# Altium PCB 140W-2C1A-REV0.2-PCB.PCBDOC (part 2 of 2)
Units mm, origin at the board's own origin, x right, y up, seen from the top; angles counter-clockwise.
Board outline 106.75 x 106.95 mm, 4 copper layers (Top Layer, MidLayer1, MidLayer2, Bottom Layer); 108 components, 173 nets, 312 pads, 723 vias.
Unrouted connection lines stored in the file: 15.
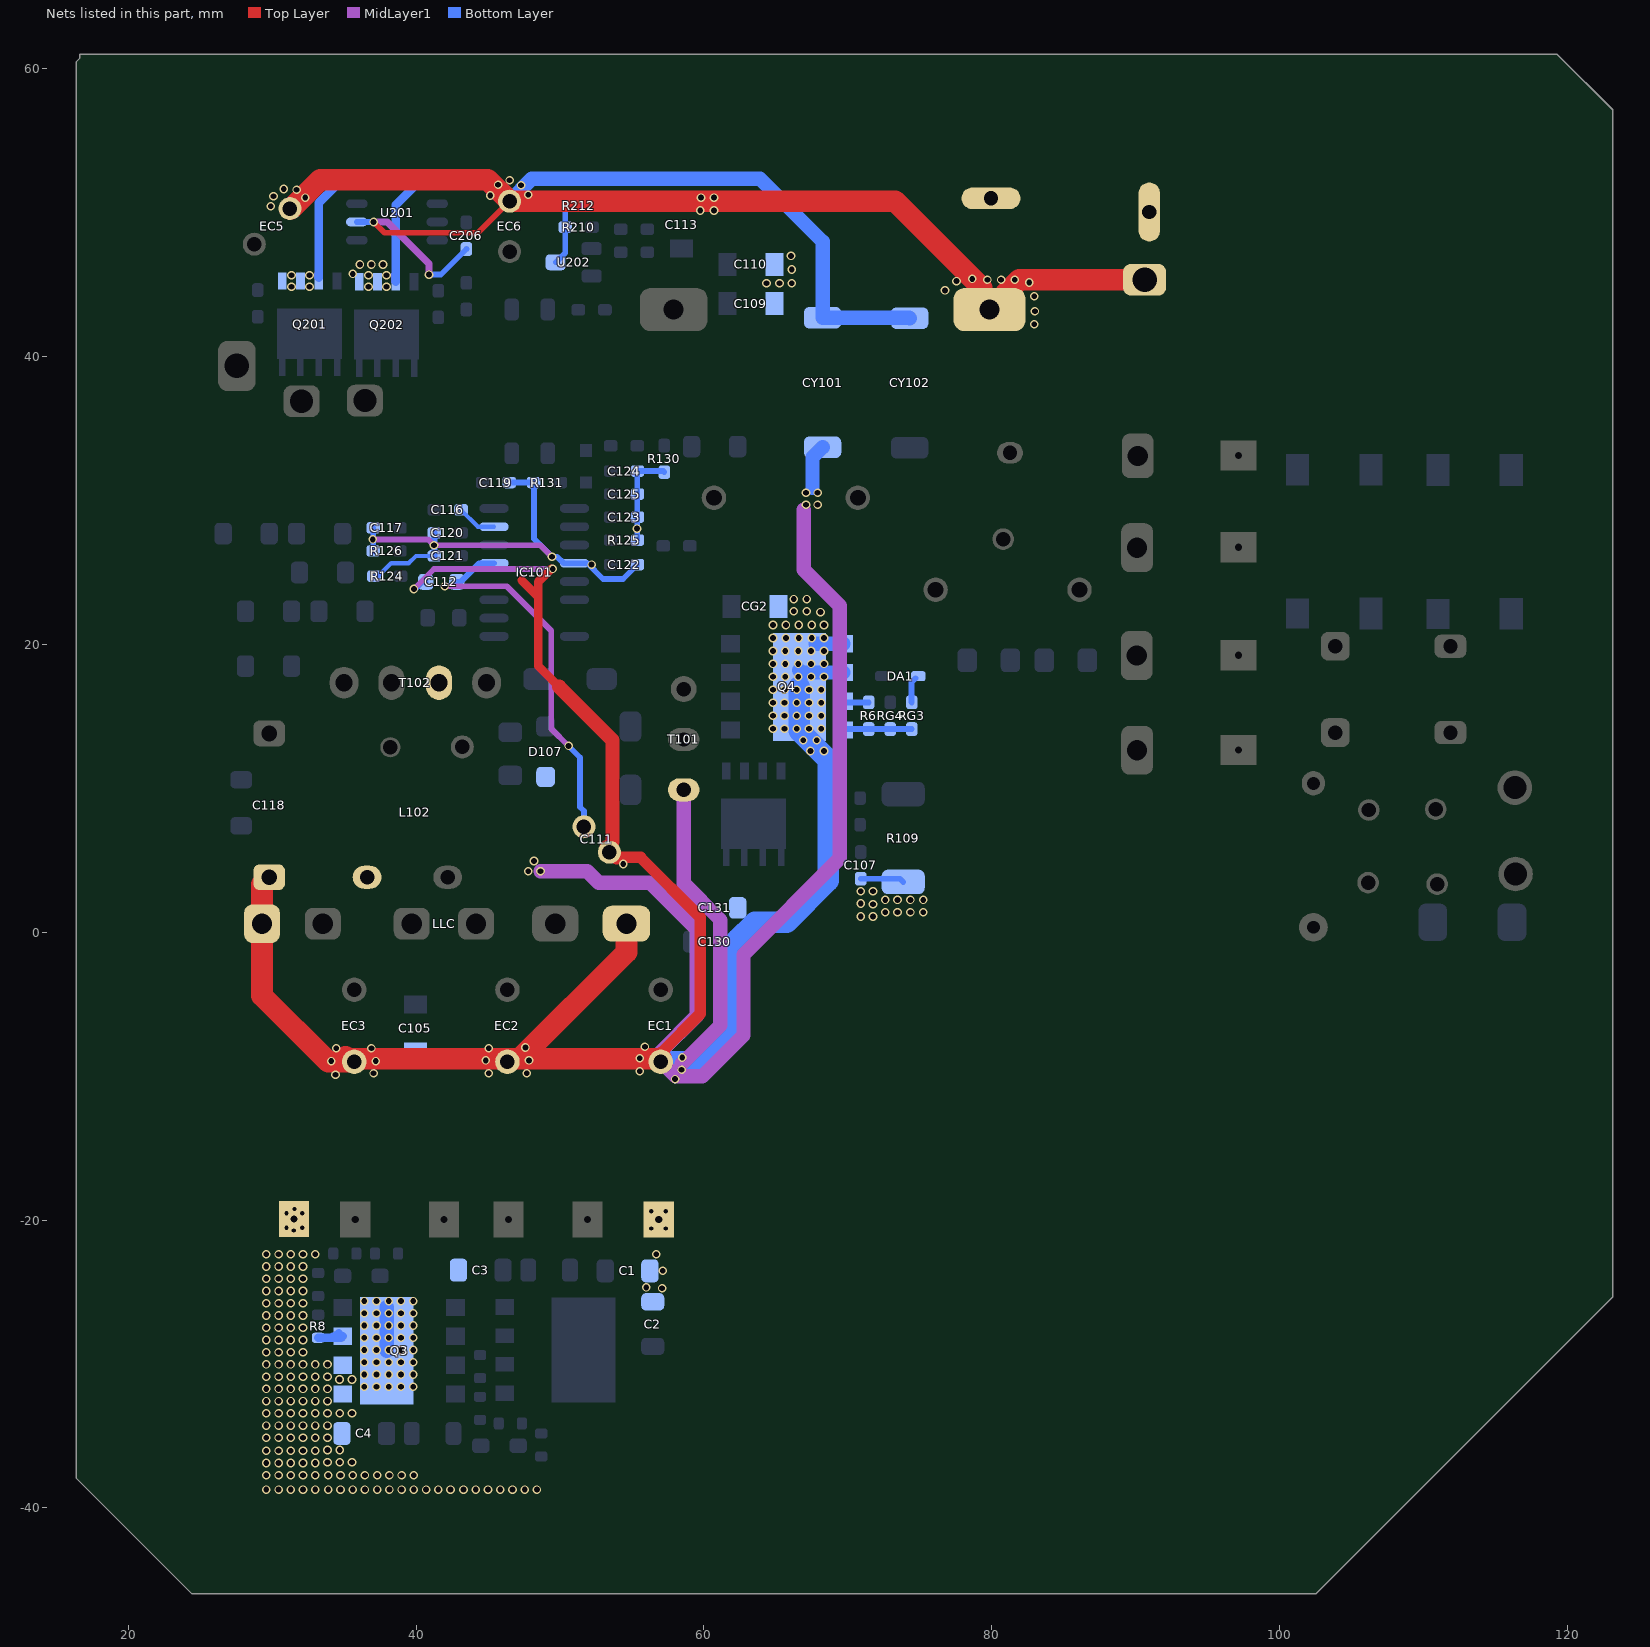
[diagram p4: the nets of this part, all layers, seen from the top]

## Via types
v1: diameter 0.6, hole 0.4, Top Layer to Bottom Layer, tented both sides, 674 vias
v2: diameter 0.65, hole 0.5, Top Layer to Bottom Layer, 27 vias
v3: diameter 0.5, hole 0.3, Top Layer to Bottom Layer, 22 vias

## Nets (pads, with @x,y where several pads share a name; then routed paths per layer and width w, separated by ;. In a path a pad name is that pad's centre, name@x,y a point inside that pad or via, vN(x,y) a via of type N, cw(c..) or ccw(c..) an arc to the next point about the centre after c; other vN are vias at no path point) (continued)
PGND: C1.2 C2.2 C3.1 C4.2 C105.1 C107.1 C111.2 C112.2 C117.1 C118.1 C119.2 C120.1 C121.1 C122.1 C123.1 C124.1 C125.1 C130.2 C131.2 CG2.1 CY101.2 EC1.2 EC2.2 EC3.2 IC101.4 L102.2 LLC.1 LLC.6 pad.2@31.52,-19.925 pad.2@56.87,-19.95 Q3.S Q4.S R6.1 R8.1 R109.1 R124.1 R125.1 R126.1 R130.2 R131.1 T101.3 T102.3 | length 291.6
  Top Layer w0.6: 47.35,24.45 48.5,23.3 ; v1@49.4,25.25 48.5,24.35 48.5,23.3 ; 49.95,17.05 48.5,18.5 48.5,23.3
  Top Layer w0.8: C111.2@53.95,5.2 55.6,5.2 59.75,1.05 59.75,-5.65 57.05,-8.35 EC1.2@57.05,-8.8
  Top Layer w1: 49.95,17.05 53.65,13.35 C111.2@53.65,6.3 ; C111.2@53.25,5.9 C111.2@53.95,5.2
  Top Layer w1.5: C118.1@29.797,3.823 29.297,3.323 LLC.6@29.297,0.598 29.297,-4.397 33.9,-9 EC3.2@35.7,-9 ; EC3.2@35.1,-8.651 35.249,-8.8 47.2,-8.8 ; LLC.1@54.622,0.598 54.622,-1.378 47.2,-8.8 ; EC1.2@57.05,-8.8 47.2,-8.8
  MidLayer1 w0.4: v1(37,27.3) 40.85,27.3 v1(41.25,26.9) 48.65,26.9 v1(49.45,26.1) ; v1(39.85,23.85) 41.25,25.25 v1(49.5,25.25)
  MidLayer1 w1: C118.1@29.797,3.823 C118.1@29.799,3.825 ; v1(48.65,4.25) 51.9,4.25 52.7,3.45 56.25,3.45 59.5,0.2 59.5,-5.8 56.95,-8.35 56.95,-8.9 58.05,-10 59.9,-10 62.75,-7.15 62.75,-1.55 69.45,5.15 69.45,22.7 66.95,25.2 66.95,29.35 ; 58.475,-9.125 61.15,-6.45 61.15,0.85 58.6,3.4 T101.3@58.6,9.9
  Bottom Layer w0.3: R124.1@37.075,24.75 37.376,24.75 38.276,25.65 39.5,25.65 40,26.15 C121.1@41.275,26.15
  Bottom Layer w0.4: R126.1@37.025,26.5 C117.1@37.025,28.1 ; v1@39.95,23.85 40.45,24.35 C112.2@40.675,24.35 ; C121.1@41.275,26.15 C120.1@41.275,27.75 ; C119.2@46.475,31.25 R131.1@48.175,31.25 ; R131.1@48.2,31.15 48.2,27.35 v1(49.45,26.1) 49.8,26.1 50.26,25.64 IC101.4@51.007,25.64 51.91,25.64 53,24.55 54.375,24.55 C122.1@55.375,25.55 ; R125.1@55.375,27.3 C123.1@55.375,28.85 C125.1@55.375,30.45 C124.1@55.375,32.05 57.175,32.05 R130.2@57.25,31.975 ; Q4.S@69.7,16.05 69.775,15.975 R6.1@71.45,15.975 ; C107.1@70.9,3.725 73.625,3.725 R109.1@73.85,3.5
  Bottom Layer w0.6: R8.1@33.198,-28.175 34.798,-28.175 Q3.S@34.898,-28.075 ; 33.882,-28.175 ccw(c33.882,-27.109) Q3.S@34.636,-27.863
  Bottom Layer w1: Q3.S@37.961,-29.075 Q3.S@37.961,-26.062 ; Q4.S@66.637,18.2 66.787,18.05 Q4.S@69.7,18.05 ; 67.55,30.9 67.55,33.001 CY101.2@68.247,33.698 ; Q4.S@67.775,20.05 Q4.S@69.7,20.05
  Bottom Layer w1.5: EC1.2@57,-9 59.9,-9 62.25,-6.65 62.25,-0.6 63.55,0.7 65.75,0.7 68.65,3.6 68.65,12 66.637,14.013 Q4.S@66.637,17.05
  other v1: 29.598,-38.725 30.448,-38.725 31.298,-38.725 32.148,-38.725 32.998,-38.725 33.898,-38.725 34.748,-38.725 35.598,-38.725 36.448,-38.725 37.298,-38.725 38.148,-38.725 38.998,-38.725 39.848,-38.725 40.698,-38.725 41.548,-38.725 42.398,-38.725 43.298,-38.725 44.148,-38.725 44.998,-38.725 45.848,-38.725 46.698,-38.725 47.548,-38.725 48.398,-38.725 29.598,-37.725 30.448,-37.725 31.298,-37.725 32.148,-37.725 32.998,-37.725 33.898,-37.725 34.748,-37.725 35.598,-37.725 36.448,-37.725 37.298,-37.725 38.148,-37.725 38.998,-37.725 39.848,-37.725 29.598,-36.875 30.448,-36.875 31.298,-36.875 32.148,-36.875 32.998,-36.875 33.848,-36.825 34.698,-36.825 35.548,-36.825 29.598,-36.025 30.448,-36.025 31.298,-36.025 32.148,-36.025 32.998,-36.025 33.848,-35.975 34.698,-35.975 29.598,-35.125 30.448,-35.125 31.298,-35.125 32.148,-35.125 32.998,-35.125 33.848,-35.125 29.598,-34.275 30.448,-34.275 31.298,-34.275 32.148,-34.275 32.998,-34.275 33.848,-34.275 29.598,-33.425 30.448,-33.425 31.298,-33.425 32.148,-33.425 32.998,-33.425 33.848,-33.425 34.698,-33.425 35.548,-33.425 29.598,-32.575 30.448,-32.575 31.298,-32.575 32.148,-32.575 32.998,-32.575 33.848,-32.575 29.598,-31.725 30.448,-31.725 31.298,-31.725 32.148,-31.725 32.998,-31.725 33.848,-31.725 36.398,-31.575 37.248,-31.575 38.098,-31.575 38.948,-31.575 39.798,-31.575 34.685,-31.075 35.548,-31.075 29.598,-30.875 30.448,-30.875 31.298,-30.875 32.148,-30.875 32.998,-30.875 33.848,-30.875 36.398,-30.725 37.248,-30.725 38.098,-30.725 38.948,-30.725 39.798,-30.725 29.598,-30.025 30.448,-30.025 31.298,-30.025 32.148,-30.025 32.998,-30.025 33.848,-30.025 36.398,-29.875 37.248,-29.875 38.098,-29.875 38.948,-29.875 39.798,-29.875 29.598,-29.175 30.448,-29.175 31.298,-29.175 32.148,-29.175 36.398,-29.025 37.248,-29.025 38.098,-29.025 38.948,-29.025 39.798,-29.025 29.598,-28.325 30.448,-28.325 31.298,-28.325 32.148,-28.325 36.398,-28.175 37.248,-28.175 38.098,-28.175 38.948,-28.175 39.798,-28.175 29.598,-27.475 30.448,-27.475 31.298,-27.475 32.148,-27.475 36.398,-27.325 37.248,-27.325 38.098,-27.325 38.948,-27.325 39.798,-27.325 29.598,-26.625 30.448,-26.625 31.298,-26.625 32.148,-26.625 36.398,-26.475 37.248,-26.475 38.098,-26.475 38.948,-26.475 39.798,-26.475 29.598,-25.775 30.448,-25.775 31.298,-25.775 32.148,-25.775 36.398,-25.625 37.248,-25.625 38.098,-25.625 38.948,-25.625 39.798,-25.625 29.598,-24.925 30.448,-24.925 31.298,-24.925 32.148,-24.925 57.098,-24.725 55.998,-24.675 29.598,-24.075 30.448,-24.075 31.298,-24.075 32.148,-24.075 57.148,-23.525 29.598,-23.225 30.448,-23.225 31.298,-23.225 32.148,-23.225 29.598,-22.375 30.448,-22.375 31.298,-22.375 32.148,-22.375 32.998,-22.375 56.698,-22.375 58,-10.2 34.4,-9.9 37.05,-9.8 45.05,-9.8 47.7,-9.8 55.55,-9.65 58.45,-9.55 34.1,-8.95 37.2,-8.95 44.85,-8.9 47.85,-8.9 55.55,-8.75 58.5,-8.7 34.45,-8.05 36.9,-8.05 45.05,-8.05 47.6,-8 55.9,-7.95 70.9,1.1 71.75,1.1 72.6,1.4 73.45,1.4 74.35,1.4 75.25,1.4 71.75,1.95 70.9,2 72.6,2.25 73.45,2.25 74.35,2.25 75.25,2.25 70.9,2.85 71.75,2.85 47.8,4.25 54.4,4.75 48.2,4.95 67.4,12.6 68.35,12.6 66.9,13.35 67.85,13.35 64.8,14.15 65.6,14.15 66.45,14.15 67.3,14.15 68.15,14.15 64.8,15.05 65.6,15.05 66.45,15.05 67.3,15.05 68.15,15.05 64.8,15.95 65.6,15.95 66.45,15.95 67.3,15.95 68.15,15.95 64.8,16.85 65.6,16.85 66.45,16.85 67.3,16.85 68.15,16.85 64.8,17.75 65.65,17.75 66.55,17.75 67.45,17.75 68.35,17.75 64.8,18.65 65.65,18.65 66.55,18.65 67.45,18.65 68.35,18.65 64.8,19.55 65.65,19.55 66.55,19.55 67.45,19.55 68.35,19.55 64.8,20.45 65.7,20.45 66.6,20.45 67.5,20.45 68.35,20.45 64.8,21.35 65.7,21.35 66.6,21.35 67.5,21.35 68.35,21.35 68.1,22.25 66.25,22.3 67.15,22.3 66.25,23.15 67.15,23.15 52.2,25.55 55.35,28.05 67.1,29.7 67.9,29.7 67.1,30.55 67.9,30.55
  other v3: 31.5,-20.725 56.35,-20.575 57.35,-20.575 30.995,-20.525 32.1,-20.525 30.995,-19.525 32.1,-19.525 56.35,-19.375 57.35,-19.375 31.55,-19.225
Q101_1: 
Q101_2: Q4.G R6.2 RG3.1 RG4.1 | length 4.8
  Bottom Layer w0.4: Q4.G@69.7,14.05 69.775,14.125 RG4.1@72.95,14.125 RG3.1@74.45,14.125
Q101_3: 
Q101_4: 
RG3_2: DA1.1 RG3.2 | length 1.8
  Bottom Layer w0.4: RG3.2@74.45,15.975 74.425,16 74.425,17.375 DA1.1@74.7,17.65
SCL: 
SCL1: 
SCL2: 
SDA: 
SDA1: 
SDA2: 
SGND: C109.1 C110.2 C113.1 C206.2 CY101.1 CY102.1 EC5.2 EC6.2 pad.0@79.95,51 pad.0@90.95,50.05 pad.0@90.625,45.342 pad.2@79.85,43.267 Q201.1S Q201.2S Q201.3S Q202.1S Q202.2S Q202.3S R210.1 R212.1 U201.2GND U201.4SSB U201.5SSA U202.2 | length 146.2
  Top Layer w0.4: EC5.2@31.237,50.287 EC5.2@31.675,49.85 ; v1(37.05,49.35) 37.8,48.6 44.3,48.6 EC6.2@46.5,50.8
  Top Layer w1.5: EC5.2@31.237,50.287 31.337,50.287 33.354,52.304 44.996,52.304 EC6.2@46.5,50.8 73.3,50.8 79.3,44.8 ; pad.2@79.85,43.267 81.925,45.342 pad.0@90.625,45.342
  MidLayer1 w0.5: v1(37.05,49.35) 38,49.35 40.9,46.45 v1(40.9,45.7)
  Bottom Layer w0.4: U201.2GND@35.886,49.357 35.893,49.35 v1(37.05,49.35) ; v1(40.9,45.7) 41.725,45.7 C206.2@43.5,47.475 ; EC6.2@46.5,50.8 47.05,50.25 R212.1@50.375,50.25 ; U202.2@49.7,46.55 50.375,47.225 R210.1@50.375,49 R212.1@50.375,50.5
  Bottom Layer w0.6: Q201.3S@33.24,45.5 33.24,50.69 34.447,51.897 U201.4SSB@35.886,51.897 ; Q202.3S@38.59,45.2 38.59,50.54 39.947,51.897 U201.5SSA@41.473,51.897
  Bottom Layer w1: EC6.2@46.5,50.8 48.05,52.35 63.9,52.35 68.247,48.003 CY101.1@68.247,42.698 74.272,42.698 CY102.1@74.297,42.673
  other v1: 82.95,42.25 83,43.15 82.95,44.2 76.75,44.6 31.35,44.85 32.6,44.85 36.7,44.85 37.95,44.85 64.35,45.1 65.25,45.1 66.1,45.1 82.6,45.15 77.55,45.25 79.7,45.35 80.65,45.35 81.6,45.35 78.65,45.4 31.35,45.65 32.6,45.65 36.7,45.65 37.95,45.65 35.6,45.75 66.1,46.05 36.1,46.4 36.9,46.4 37.7,46.4 66.05,47 59.75,50.15 60.7,50.15 29.9,50.45 32.3,51.05 59.8,51.05 60.7,51.05 30.1,51.15 45.15,51.2 47.8,51.25 31.7,51.6 30.8,51.65 47.3,51.9 45.7,51.95 46.5,52.25
SNSCURLLC: C116.2 IC101.15 | length 2.8
  Bottom Layer w0.3: C116.2@43.125,29.35 44.295,28.18 IC101.15@45.419,28.18
VCC: C111.1 C112.1 D107.2 IC101.13 | length 27.3
  MidLayer1 w0.4: v1(42,24.05) 46.3,24.05 49.4,20.95 49.4,14.15 v1(50.6,12.95)
  Bottom Layer w0.4: v1(42,24.05) 42.525,24.05 C112.1@42.825,24.35 43.1,24.35 44.39,25.64 IC101.13@45.419,25.64 ; v1(50.6,12.95) 51.4,12.15 51.4,8.7 51.666,8.434 C111.1@51.666,7.334
VDD: 
VDRV: 
VDRV1: 
VDRV2: 
VIN20: 
pads on no net: IC101.7 IC101.12 L102.4

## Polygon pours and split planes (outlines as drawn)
PGND on Top Layer "Keep-Out Layer-No Net" (solid, remove dead copper, pour order 533): 57.898,-25.825 57.448,-26.275 55.948,-26.275 55.648,-25.975 55.648,-21.475 55.798,-21.325 55.798,-20.575 57.498,-20.575 57.898,-20.975
NetC101_1 on Top Layer "Keep-Out Layer-No Net" (solid, remove dead copper, pour order 531): 20 vertices, not listed, extent 48.698,-39.725 57.448,-20.675
PGND on Top Layer "Keep-Out Layer-No Net" (solid, remove dead copper, pour order 529): 20 vertices, not listed, extent 29.098,-39.725 49.198,-20.625
NetC108_1 on Top Layer "Keep-Out Layer-No Net" (solid, remove dead copper, pour order 527): 42.998,-21.425 44.398,-22.825 44.398,-24.525 45.598,-25.725 45.598,-27.725 45.398,-27.925 42.598,-27.925 42.048,-27.375 42.048,-23.325 40.898,-22.175 40.898,-20.625 42.848,-20.625 42.998,-20.775
PGND on Top Layer "Bottom Layer-No Net 1" (solid, remove dead copper, pour order 445): 40.45,10.45 41.1,9.8 41.1,7 39.75,5.65 37.4,3.3 31.9,3.3 26,3.3 25.6,3.7 25.6,9.15 26.65,10.2 26.9,10.45 32.75,10.45
NetQ201_5 on Top Layer "Bottom Layer-No Net 1" (solid, remove dead copper, pour order 417): 22 vertices, not listed, extent 34.8,35.8 41.35,43.55
NetQ201_7 on Top Layer "Bottom Layer-No Net 1" (solid, remove dead copper, pour order 415): 19 vertices, not listed, extent 29.4,35.8 34.95,43.55
+20V on Top Layer "Bottom Layer-No Net 1" (solid, remove dead copper, pour order 413): 45.5,48.55 46.9,48.55 47.15,48.3 48.05,48.3 57.15,48.3 60.8,44.65 61.35,44.1 61.35,42.95 61.35,42.1 61,41.75 59.85,41.75 45.95,41.75 44.8,42.9 44.8,47.85 45.5,48.55
+20V on Top Layer "Bottom Layer-No Net 1" (solid, remove dead copper, pour order 411): 23 vertices, not listed, extent 25.25,36.95 29.75,49.45
SGND on Top Layer "Bottom Layer-No Net 1" (solid, remove dead copper, pour order 409): 47 vertices, not listed, extent 28.55,41.8 92.9,53.05
PGND on Top Layer "Bottom Layer-No Net 1" (solid, remove dead copper, pour order 373): 17 vertices, not listed, extent 30.5,2.65 37.75,5.3
PGND on Top Layer "Bottom Layer-No Net 1" (solid, remove dead copper, pour order 353): 29 vertices, not listed, extent 25.55,19.9 58.6,34.4
NetC108_1 on Top Layer "Bottom Layer-No Net 1" (solid, remove dead copper, pour order 347): 18 vertices, not listed, extent 38.2,-0.5 43.25,4.7
PGND on Top Layer "Bottom Layer-No Net 1" (solid, remove dead copper, pour order 345): 67.2,28.95 67.9,28.25 67.9,24.65 69.2,23.35 69.25,23.3 69.25,22.75 64.45,22.75 64.4,22.8 62.25,24.95 62.25,27.5 63.7,28.95
NetC101_1 on Top Layer "Bottom Layer-No Net 1" (solid, remove dead copper, pour order 343): 19 vertices, not listed, extent 58,4.05 66.05,9.35
PGND on Top Layer "Bottom Layer-No Net 1" (solid, remove dead copper, pour order 341): 32 vertices, not listed, extent 48.2,-5.1 60.15,26.45
PGND on Top Layer "Bottom Layer-No Net 1" (solid, remove dead copper, pour order 339): 68 vertices, not listed, extent 25.6,-11.35 75.55,5.3
PGND on Top Layer "Bottom Layer-No Net 1" (solid, remove dead copper, pour order 337): 18 vertices, not listed, extent 64.4,4.05 69.95,23.5
NetC114_1 on Top Layer "Keep-Out Layer-No Net" (solid, remove dead copper, pour order 277): 22 vertices, not listed, extent 28.5,12.75 36,18.4
NetL102_2 on Top Layer "Keep-Out Layer-No Net" (solid, remove dead copper, pour order 271): 38.2,18.55 39,18.55 39.2,18.35 39.2,12.4 38.85,12.05 37.7,12.05 37.3,12.45 37.3,18.1 37.75,18.55
NetBD101_2 on Top Layer "Keep-Out Layer-No Net" (solid, remove dead copper, pour order 265): 111.5,23.95 117.55,23.95 118,23.5 118,23.1 118,18.5 117.5,18 117.2,18 110.5,18 110.1,18.4 110.05,18.45 110.05,18.65 110.05,23.55 110.4,23.9 110.45,23.95 111.4,23.95
NetBD101_4 on Top Layer "Keep-Out Layer-No Net" (solid, remove dead copper, pour order 250): 117.6,33.95 118,33.55 118,28.6 117.25,27.85 102.6,27.85 100.45,25.7 97.35,25.7 97.35,27.75 97.4,27.8 98.65,27.8 99.1,28.25 99.1,30.35 100.05,31.3 100.05,33.35 100.65,33.95
NetBD101_3 on Top Layer "Keep-Out Layer-No Net" (solid, remove dead copper, pour order 264): 106.9,22.2 107.55,21.55 107.55,18.45 107.1,18 98.65,18 98.45,18.2 97.7,18.2 97.7,20.25 97.75,20.3 98.65,20.3 98.8,20.45 98.8,21.5 99.5,22.2
NetCX101_2 on Top Layer "Keep-Out Layer-No Net" (solid, remove dead copper, pour order 266): 47 vertices, not listed, extent 98.1,-0.9 107.1,15.1
NetCX101_1 on Top Layer "Keep-Out Layer-No Net" (solid, remove dead copper, pour order 246): 21 vertices, not listed, extent 101.55,7.35 113.35,14.95
NetCN101_N on Top Layer "Keep-Out Layer-No Net" (solid, remove dead copper, pour order 243): 117.45,11.7 117.75,11.4 117.75,9.35 117.25,8.85 113.9,8.85 112.55,7.5 110.2,7.5 109.85,7.85 109.85,9 111.7,10.85 114.05,10.85 114.9,11.7
NetBD1 on Top Layer "Keep-Out Layer-No Net" (solid, remove dead copper, pour order 269): 82.35,34.55 82.8,34.1 82.8,32.9 82.45,32.55 74.15,32.55 65.05,32.55 60.7,28.2 60.7,16.55 60.1,15.95 57.35,15.95 57.15,16.15 57.15,29.25 62.45,34.55
NetBD101_4 on Top Layer "Keep-Out Layer-No Net" (solid, remove dead copper, pour order 279): 23 vertices, not listed, extent 68.75,8.65 92.25,31.05
PGND on Bottom Layer "Keep-Out Layer-No Net" (solid, remove dead copper, pour order 545): 57.898,-20.575 57.898,-25.825 57.448,-26.275 55.798,-26.275 55.648,-26.125 55.648,-24.025 55.648,-21.475 55.798,-21.325 55.798,-20.575 57.848,-20.575
NetC101_1 on Bottom Layer "Keep-Out Layer-No Net" (solid, remove dead copper, pour order 543): 20 vertices, not listed, extent 48.698,-39.725 57.448,-19.925
113 on Bottom Layer "Keep-Out Layer-No Net" (solid, remove dead copper, pour order 541): 46.248,-22.675 48.198,-22.675 48.348,-22.825 48.348,-23.175 48.348,-24.125 48.198,-24.275 47.798,-24.275 45.598,-24.275 45.498,-24.175 45.448,-24.125 45.448,-23.875 45.448,-22.825 45.598,-22.675 45.848,-22.675
PGND on Bottom Layer "Keep-Out Layer-No Net" (solid, remove dead copper, pour order 539): 39 vertices, not listed, extent 29.098,-39.725 49.198,-20.825
NetC108_1 on Bottom Layer "Keep-Out Layer-No Net" (solid, remove dead copper, pour order 537): 46.798,-25.475 46.898,-25.575 46.898,-28.475 46.748,-28.625 43.898,-28.625 43.448,-29.075 43.448,-35.375 43.198,-35.625 42.198,-35.625 41.998,-35.425 41.998,-25.575 42.098,-25.475
115 on Bottom Layer "Keep-Out Layer-No Net" (solid, remove dead copper, pour order 535): 38.648,-34.025 40.098,-34.025 40.248,-34.175 40.248,-34.275 40.248,-35.475 40.098,-35.625 39.898,-35.625 37.498,-35.625 37.398,-35.525 37.348,-35.475 37.348,-35.075 37.348,-34.175 37.448,-34.075 37.498,-34.025 38.398,-34.025
SGND on Bottom Layer "Bottom Layer-No Net 1" (solid, remove dead copper, pour order 407): 18 vertices, not listed, extent 69.75,41.8 92.9,53.05
SGND on Bottom Layer "Bottom Layer-No Net 1" (solid, remove dead copper, pour order 405): 37 vertices, not listed, extent 28.95,41.8 75.7,53.05
SGND on Bottom Layer "Bottom Layer-No Net 1" (solid, remove dead copper, pour order 403): 19 vertices, not listed, extent 57.3,42.45 66.45,51.45
+20V on Bottom Layer "Bottom Layer-No Net 1" (solid, remove dead copper, pour order 401): 20 vertices, not listed, extent 54.15,41.75 62.65,49.587
+20V on Bottom Layer "Bottom Layer-No Net 1" (solid, remove dead copper, pour order 399): 18 vertices, not listed, extent 44.2,45.75 48.2,48.8
SGND on Bottom Layer "Bottom Layer-No Net 1" (solid, remove dead copper, pour order 397): 20 vertices, not listed, extent 35.3,44.55 39,47.3
+20V on Bottom Layer "Bottom Layer-No Net 1" (solid, remove dead copper, pour order 395): 18 vertices, not listed, extent 25.25,36.95 29.75,50.05
SGND on Bottom Layer "Bottom Layer-No Net 1" (solid, remove dead copper, pour order 393): 27 vertices, not listed, extent 28.95,44.55 33.65,52.75
NetQ201_7 on Bottom Layer "Bottom Layer-No Net 1" (solid, remove dead copper, pour order 391): 18 vertices, not listed, extent 29,35.8 34.95,43.55
NetQ201_5 on Bottom Layer "Bottom Layer-No Net 1" (solid, remove dead copper, pour order 389): 18 vertices, not listed, extent 34.8,35.8 41.35,43.55
VCC on Bottom Layer "Bottom Layer-No Net 1" (solid, remove dead copper, pour order 351): 30 vertices, not listed, extent 48.25,6.25 52.65,11.55
NetBD1 on Bottom Layer "Bottom Layer-No Net 1" (solid, remove dead copper, pour order 335): 17 vertices, not listed, extent 54.15,14.05 59.7,17.95
PGND on Bottom Layer "Bottom Layer-No Net 1" (solid, remove dead copper, pour order 333): 53.4,6.6 53.85,6.6 54.25,6.2 54.7,5.75 54.7,4.5 54.45,4.25 53.55,4.25 53.15,4.25 52.45,4.95 52.3,5.1 52.3,5.55 52.3,5.7 53.15,6.55 53.2,6.6 53.3,6.6
NetC107_2 on Bottom Layer "Top Overlay-No Net" (hatched 90Degree grid 0.1 track 0.203, pour order 245): -274.888,-89.395 -274.782,-89.288 -274.742,-89.288
NetD107_1 on Bottom Layer "Bottom Solder-No Net" (solid, remove dead copper, pour order 254): 17 vertices, not listed, extent 43.872,13.2 47.225,18.423
NetCN101_L on Bottom Layer "Keep-Out Layer-No Net" (solid, remove dead copper, pour order 240): 116.55,5.45 117.55,5.45 117.95,5.05 117.95,-0.5 117.6,-0.85 115.45,-0.85 115.05,-0.45 115.05,4.15 115.05,4.75 115.65,5.35 115.75,5.45 116.25,5.45
NetF101_2 on Bottom Layer "Keep-Out Layer-No Net" (solid, remove dead copper, pour order 241): 110.8,4.55 111.45,4.55 111.75,4.25 111.75,3.1 111.75,-0.55 111.45,-0.85 109.9,-0.85 109.5,-0.45 109.5,3.85 110.2,4.55
NetCN101_N on Bottom Layer "Keep-Out Layer-No Net" (solid, remove dead copper, pour order 242): 117.45,11.7 117.75,11.4 117.75,9.1 117.3,8.65 114.05,8.65 112.9,7.5 110.2,7.5 109.85,7.85 109.85,9 111.7,10.85 114.05,10.85 114.9,11.7
NetCX101_2 on Bottom Layer "Keep-Out Layer-No Net" (solid, remove dead copper, pour order 247): 27 vertices, not listed, extent 97.85,-0.9 107.1,15.1
NetBD101_4 on Bottom Layer "Keep-Out Layer-No Net" (solid, remove dead copper, pour order 260): 106.05,33.95 107.65,33.95 107.85,33.75 107.85,31.25 107.6,31 104.95,31 104.7,31.25 104.65,31.3 104.65,33.2 104.65,33.7 104.85,33.9 104.9,33.95 105.7,33.95
NetBD101_1 on Bottom Layer "Keep-Out Layer-No Net" (solid, remove dead copper, pour order 261): 34 vertices, not listed, extent 97.55,27.85 112.8,34.15
NetBD101_3 on Bottom Layer "Keep-Out Layer-No Net" (solid, remove dead copper, pour order 263): 20 vertices, not listed, extent 98.3,18 107.55,23.95
NetBD101_2 on Bottom Layer "Keep-Out Layer-No Net" (solid, remove dead copper, pour order 262): 117.55,23.95 118,23.5 118,18.55 117.45,18 110.5,18 110.05,18.45 110.05,23.55 110.45,23.95
NetCX101_1 on Bottom Layer "Keep-Out Layer-No Net" (solid, remove dead copper, pour order 244): 21 vertices, not listed, extent 101.55,7.35 113.35,14.95
NetBD101_4 on Bottom Layer "Keep-Out Layer-No Net" (solid, remove dead copper, pour order 259): 117.7,33.85 118,33.55 118,30.05 117.3,29.35 114.9,29.35 114.35,29.9 114.35,33.6 114.6,33.85
PGND on Bottom Layer "Keep-Out Layer-No Net" (solid, remove dead copper, pour order 276): 71.75,4.35 75.25,4.35 75.55,4.05 75.55,-0.9 75.15,-1.3 70.9,-1.3 70.5,-0.9 70.5,4.15 70.65,4.3 70.7,4.35 71.5,4.35
NetBD101_4 on Bottom Layer "Keep-Out Layer-No Net" (solid, remove dead copper, pour order 278): 72.4,12 75.2,12 75.45,11.75 75.45,9.45 75.45,8.95 75.25,8.75 70.65,8.75 70.4,9 70.4,11.8 70.6,12 72,12
NetBD101_4 on Bottom Layer "Keep-Out Layer-No Net" (solid, remove dead copper, pour order 280): 90.9,28.55 91.95,28.55 92.25,28.25 92.25,27.9 92.25,25.1 91.85,24.7 89.4,24.7 89,25.1 89,28.2 89.35,28.55 90.4,28.55
NetCX101_2 on Bottom Layer "Keep-Out Layer-No Net" (solid, remove dead copper, pour order 282): 89.9,14.55 91.5,14.55 91.95,14.1 91.95,10.85 91.45,10.35 89.5,10.35 89.05,10.35 88.6,10.8 88.6,14.05 88.95,14.4 89.1,14.55 89.5,14.55
NetBD101_3 on Bottom Layer "Keep-Out Layer-No Net" (solid, remove dead copper, pour order 284): 18 vertices, not listed, extent 87.1,17.5 92.25,21.3
NetBD101_4 on Bottom Layer "Keep-Out Layer-No Net" (solid, remove dead copper, pour order 281): 71.15,31.2 72.4,29.95 72.4,29.55 77.4,24.55 77.4,23 77.1,22.7 75.8,22.7 72.65,25.85 72.65,26.9 69.7,29.85 69.7,30.65 70.25,31.2
NetBD101_1 on Bottom Layer "Keep-Out Layer-No Net" (solid, remove dead copper, pour order 268): 21 vertices, not listed, extent 78.7,22.25 92.15,34.65
NetBD1 on Bottom Layer "Keep-Out Layer-No Net" (solid, remove dead copper, pour order 286): 82.2,34.55 82.65,34.1 82.65,32.25 82.1,31.7 79.8,31.7 79.45,32.05 79.45,34.2 79.8,34.55
NetCX101_2 on Bottom Layer "Keep-Out Layer-No Net" (solid, remove dead copper, pour order 287): 76.1,34.55 76.8,33.85 76.8,28.95 76.55,28.7 75.5,28.7 74.5,29.7 74.5,31.4 72.9,33 72.9,34.2 73.25,34.55
PGND on Bottom Layer "Keep-Out Layer-No Net" (solid, remove dead copper, pour order 288): 18 vertices, not listed, extent 66.6,29.4 69.8,34.55
NetBD1 on Bottom Layer "Keep-Out Layer-No Net" (solid, remove dead copper, pour order 291): 60.25,31.35 61.45,31.35 61.8,31 61.9,30.9 62,30.8 62,30.15 62,29.45 61.65,29.1 59.15,29.1 58.8,29.45 58.8,30.25 59.8,31.25 59.9,31.35 60.1,31.35
PGND on Bottom Layer "Keep-Out Layer-No Net" (solid, remove dead copper, pour order 293): 58.45,10.85 59.4,10.85 59.7,10.55 59.7,9.4 59.5,9.2 59.35,9.05 58.75,9.05 57.95,9.05 57.55,9.45 57.4,9.6 57.4,10.05 57.4,10.5 57.7,10.8 57.75,10.85 58,10.85
NetC101_2 on Bottom Layer "Keep-Out Layer-No Net" (solid, remove dead copper, pour order 270): 27 vertices, not listed, extent 57.5,10.55 65.85,23.5
PGND on Bottom Layer "Keep-Out Layer-No Net" (solid, remove dead copper, pour order 294): 56,1.9 56.3,1.6 56.3,-0.4 56.05,-0.65 53.2,-0.65 52.95,-0.4 52.95,1.6 53.25,1.9
NetC101_1 on Bottom Layer "Keep-Out Layer-No Net" (solid, remove dead copper, pour order 273): 37 vertices, not listed, extent 33.2,-5.8 66.05,9.85
PGND on Bottom Layer "Keep-Out Layer-No Net" (solid, remove dead copper, pour order 275): 35 vertices, not listed, extent 26.05,-11.3 72.35,23.5
PGND on Bottom Layer "Keep-Out Layer-No Net" (solid, remove dead copper, pour order 295): 30.55,4.9 30.95,4.5 30.95,2.75 30.6,2.4 30.6,-0.7 30.4,-0.9 28.25,-0.9 27.45,-0.1 27.45,3.95 28.4,4.9
NetD106_1 on Bottom Layer "Keep-Out Layer-No Net" (solid, remove dead copper, pour order 296): 33.8,2.8 35.2,1.4 35.2,0.8 35.2,-0.3 34.85,-0.65 32.55,-0.65 32.25,-0.35 32.2,-0.3 32.2,0.8 32.2,1.7 32.65,2.15 33.3,2.8 33.8,2.8
PGND on Bottom Layer "Keep-Out Layer-No Net" (solid, remove dead copper, pour order 297): 36.45,4.65 37.6,4.65 37.9,4.35 37.9,3.7 37.4,3.2 37.15,2.95 36.65,2.95 36.05,2.95 35.7,3.3 35.55,3.45 35.55,4 35.55,4.35 35.8,4.6 35.85,4.65 36,4.65
NetIC101_9 on Bottom Layer "Keep-Out Layer-No Net" (solid, remove dead copper, pour order 299): 45.7,1.4 45.7,-0.15 45.25,-0.6 45.15,-0.7 44.8,-0.7 43,-0.7 42.7,-0.4 42.7,1.2 43.2,1.7 44.9,1.7 45.45,1.7 45.7,1.45
NetC108_1 on Bottom Layer "Keep-Out Layer-No Net" (solid, remove dead copper, pour order 298): 43,4.7 43.4,4.3 43.4,3.65 42.75,3 42.4,3 41.05,1.65 41.05,-0.4 40.75,-0.7 38.55,-0.7 38.2,-0.35 38.2,1.7 41.2,4.7
NetL102_2 on Bottom Layer "Keep-Out Layer-No Net" (solid, remove dead copper, pour order 272): 38.85,18.55 39.2,18.2 39.2,12.4 38.8,12 37.6,12 37.2,12.4 37.2,18.2 37.55,18.55
PGND on Bottom Layer "Keep-Out Layer-No Net" (solid, remove dead copper, pour order 301): 18 vertices, not listed, extent 44.55,3.95 49.1,9.3
PGND on Bottom Layer "Keep-Out Layer-No Net" (solid, remove dead copper, pour order 290): 42.4,18.55 42.85,18.1 42.85,14.95 44.25,13.55 44.25,9.95 45.75,8.45 45.75,7.4 42.3,7.4 40.7,9 40.7,18.25 41,18.55
NetC114_1 on Bottom Layer "Keep-Out Layer-No Net" (solid, remove dead copper, pour order 274): 35.65,18.45 36,18.1 36,15.15 33.6,12.75 28.8,12.75 28.4,13.15 28.4,14.95 28.55,15.1 32.5,15.1 33.85,16.45 33.85,17.95 34.35,18.45
PGND on Bottom Layer "Keep-Out Layer-No Net" (solid, remove dead copper, pour order 305): 26 vertices, not listed, extent 46.4,24.95 52.5,31.9
SGND on MidLayer1 "Bottom Layer-No Net 1" (solid, remove dead copper, pour order 441): 35.4,48.6 37.6,48.6 38.75,47.45 40,46.2 40,45.35 40,44.55 39.6,44.15 31,44.15 30.6,44.55 30.6,45.5 31.85,46.75 33.7,48.6 35.05,48.6
+20V on MidLayer1 "Bottom Layer-No Net 1" (solid, remove dead copper, pour order 439): 22 vertices, not listed, extent 25.25,36.95 30.1,49.6
NetQ201_5 on MidLayer1 "Bottom Layer-No Net 1" (solid, remove dead copper, pour order 425): 22 vertices, not listed, extent 34.8,35.8 41.35,43.55
NetQ201_7 on MidLayer1 "Bottom Layer-No Net 1" (solid, remove dead copper, pour order 427): 19 vertices, not listed, extent 29.4,35.8 34.95,43.55
+20V on MidLayer1 "Bottom Layer-No Net 1" (solid, remove dead copper, pour order 423): 57.35,48.35 60.4,45.3 61.4,44.3 61.4,43.1 61.4,42 61.15,41.75 45.2,41.75 43.25,43.7 43.25,47.35 44.05,48.15 44.25,48.35 46.2,48.35
SGND on MidLayer1 "Bottom Layer-No Net 1" (solid, remove dead copper, pour order 421): 26 vertices, not listed, extent 29.15,41.8 92.9,53.05
PGND on MidLayer1 "Bottom Layer-No Net 1" (solid, remove dead copper, pour order 381): 44 vertices, not listed, extent 25.6,-11.35 63.25,5.3
PGND on MidLayer1 "Bottom Layer-No Net 1" (solid, remove dead copper, pour order 379): 48.15,5.3 51.55,5.3 52.4,4.45 52.4,3.75 47.75,3.75 47.45,4.05 47.45,4.85 47.9,5.3
NetC101_1 on MidLayer1 "Bottom Layer-No Net 1" (solid, remove dead copper, pour order 377): 35 vertices, not listed, extent 34.35,-5.8 57.75,1.85
NetBD101_4 on MidLayer1 "Bottom Layer-No Net 1" (solid, remove dead copper, pour order 371): 28 vertices, not listed, extent 69.2,8.65 77.25,31.05
PGND on MidLayer1 "Bottom Layer-No Net 1" (solid, remove dead copper, pour order 369): 31 vertices, not listed, extent 62.25,5.1 68.65,28.95
NetC101_1 on MidLayer1 "Bottom Layer-No Net 1" (solid, remove dead copper, pour order 367): 63.35,9.4 65.8,9.4 66.05,9.15 66.05,8.85 66.05,4.85 65.45,4.25 65.25,4.05 65.15,4.05 60.7,4.05 60.35,4.4 60.3,4.45 60.3,8.05 61.2,8.95 61.65,9.4 63.1,9.4
PGND on MidLayer1 "Bottom Layer-No Net 1" (solid, remove dead copper, pour order 365): 58.35,10.85 59.4,10.85 59.7,10.55 59.75,10.5 59.75,9.9 59.75,9 58.75,8 58.7,7.95 58.15,7.95 57.4,8.7 57.4,10.25 57.4,10.45 57.8,10.85 58.1,10.85
PGND on MidLayer1 "Bottom Layer-No Net 1" (solid, remove dead copper, pour order 363): 67,30.9 68.05,30.9 68.35,30.6 68.35,29.1 67.3,28.05 67.25,28 66.45,28 66.45,30.6 66.75,30.9
NetBD101_1 on MidLayer1 "Bottom Layer-No Net 1" (solid, remove dead copper, pour order 359): 36 vertices, not listed, extent 79.9,22.45 92.05,34.65
NetCX101_2 on MidLayer1 "Bottom Layer-No Net 1" (solid, remove dead copper, pour order 357): 32 vertices, not listed, extent 75.25,10.35 91.95,30.2
NetBD1 on MidLayer1 "Bottom Layer-No Net 1" (solid, remove dead copper, pour order 355): 29 vertices, not listed, extent 57.15,15.95 82.8,34.55
PGND on MidLayer1 "Bottom Layer-No Net 1" (solid, remove dead copper, pour order 349): 27 vertices, not listed, extent 25.55,19.9 59.5,34.4
SGND on MidLayer2 "Bottom Layer-No Net 1" (solid, remove dead copper, pour order 437): 20 vertices, not listed, extent 58.85,41.8 92.85,52.85
+20V on MidLayer2 "Bottom Layer-No Net 1" (solid, remove dead copper, pour order 435): 20 vertices, not listed, extent 25.25,41.75 61.35,53.05
NetQ201_5 on MidLayer2 "Bottom Layer-No Net 1" (solid, remove dead copper, pour order 429): 22 vertices, not listed, extent 34.8,35.8 41.35,43.55
NetQ201_7 on MidLayer2 "Bottom Layer-No Net 1" (solid, remove dead copper, pour order 431): 19 vertices, not listed, extent 29.4,35.8 34.95,43.55
PGND on MidLayer2 "Bottom Layer-No Net 1" (solid, remove dead copper, pour order 387): 34 vertices, not listed, extent 25.6,-11.35 87.5,34.4
PGND on MidLayer2 "Bottom Layer-No Net 1" (solid, remove dead copper, pour order 385): 65.7,23.5 68.7,23.5 70.15,22.05 70.4,21.8 70.4,18.35 70.4,12.65 70.05,12.3 64.75,12.3 64.45,12.6 64.4,12.65 64.4,13 64.4,23.3 64.45,23.35 64.6,23.5 65.6,23.5
NetC101_1 on MidLayer2 "Bottom Layer-No Net 1" (solid, remove dead copper, pour order 383): 63.35,9.4 65.8,9.4 66.05,9.15 66.05,8.85 66.05,4.85 65.45,4.25 65.25,4.05 65.15,4.05 60.7,4.05 60.35,4.4 60.3,4.45 60.3,8.05 61.2,8.95 61.65,9.4 63.1,9.4

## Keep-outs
Keep-Out Layer:
  lines w0.1: 31.395,-40.25 57.97,-40.25

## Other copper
MidLayer1:
  pour cut-out: 52.4,25.15 52.5,25.05 52.5,23.1 52.95,22.65 52.95,22.4 51.85,22.4 51.85,22.8 52.15,23.1 52.15,25.05 52.25,25.15
  pour cut-out: 51.45,27.9 52.1,27.25 52.1,26.05 52.2,25.95 52.35,25.95 52.5,26.1 52.5,26.95 52.7,27.15 52.7,27.6 52.4,27.9
MidLayer2:
  pour cut-out: 46.35,49.05 46.3,49.1 46.3,52.7 45.9,53.1 45.9,53.4 47.05,53.4 47.1,53.35 47.1,53.1 46.6,52.6 46.6,49.1 46.55,49.05
  pour cut-out: 46.55,45.7 46.6,45.65 46.6,42.05 47,41.65 47,41.35 45.85,41.35 45.8,41.4 45.8,41.65 46.3,42.15 46.3,45.65 46.35,45.7
  pour cut-out: 30.575,2.05 31,1.625 31,-0.475 30.575,-0.9 27.975,-0.9 27.55,-0.475 27.55,1.55 28.05,2.05
  pour cut-out: 56.15,1.95 56.55,1.55 56.55,-0.25 56.05,-0.75 53.15,-0.75 52.65,-0.25 52.65,1.55 53.05,1.95
  pour cut-out: 39,-1.3 38.3,-0.6 38.3,1.813 38.997,2.51 39.96,2.51 40.402,2.952 40.402,3.928 43.953,3.928 44.002,3.879 44.002,3.048 45.05,2 45.05,-0.95 44.7,-1.3
  pour cut-out: 67.05,23.85 68.75,23.85 70.7,21.9 70.7,12.5 70.2,12 64.65,12 64.1,12.55 64.1,23.5 64.45,23.85 67,23.85 67,23.55 64.6,23.55 64.4,23.35 64.4,12.65 64.75,12.3 70.05,12.3 70.4,12.65 70.4,21.75 68.6,23.55 67.05,23.55

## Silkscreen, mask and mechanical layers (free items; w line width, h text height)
Top Overlay:
  circle w0.127: c116.4,4.05 r1
  circle w0.127: c116.35,10.05 r1
  lines w0.1: 89.5,-1.15 77.5,-1.15 77.5,11.85 89.5,11.85
  lines w0.127: 25.825,-11.833 25.825,53.367 ; 34.325,43.267 91.325,43.267 ; 51.245,43.867 51.245,53.867 54.405,53.867 54.405,43.867 ; 52.525,43.867 52.525,53.867 ; 53.125,43.867 53.125,53.867 ; 61.045,43.867 61.045,53.867 64.205,53.867 64.205,43.867 ; 62.325,43.867 62.325,53.867 ; 62.925,43.867 62.925,53.867 ; 70.75,43.867 70.75,53.867 76.5,53.867 76.5,43.867 ; 71.15,43.867 71.15,53.867 ; 76.1,43.867 76.1,53.867 ; 82.95,43.867 82.95,53.867 88.7,53.867 88.7,43.867 ; 83.35,43.867 83.35,53.867 ; 88.3,43.867 88.3,53.867 ; 92.825,-1.833 92.825,53.367 ; 91.325,43.267 91.325,42.667 34.325,42.667 34.325,43.867 91.325,43.867 91.325,43.267
  lines w0.254: 72.125,20.775 89.125,20.775 ; 91.272,-1.727 91.272,21.273
  text "SGNG" at 77.3,46.15 h2
  text "V+" at 56.65,45.9 h2
  text "140W 2C1A" at 41.5,40.35 h1.2
  text "主板V0.2" at 41.9,38.1 h1.8
  text "2022.08.30" at 41.5,35.9 h1
  text "A" at 27.1,35.5 h1.8
  text "B2" at 35.8,34.1 h1.8
  text "B1" at 31.6,34 h1.8
  text "140W 2C1A" at 102.45,29.15 h1.2
  text "EMI小板V0.2" at 102.85,26.9 h1.8
  text "2022.08.30" at 102.45,24.7 h1
  text "N" at 115.9,7.1 h2
  text "L" at 116.35,1.05 h2
  text "140W 2C1A" at 46.748,-23.125 h1.2 r270
  text "2022.11.04" at 44.948,-23.475 h1 r270
  text "D-S" at 43.398,-23.575 h1 r270
Bottom Overlay:
  lines w0.1: 36.15,32.65 36.15,24.05 36.3,23.9 38.2,23.9 37.8,23.5 ; 39.55,35 39.55,30.15 39.95,29.75 40.2,29.5 40.2,25.55 39.85,25.9 ; 56.45,52.2 56.45,51.55 57.35,52.45 61.35,52.45 62.3,51.5 62.3,48.7 62.7,48.3 66.2,48.3 ; 39.85,25.9 39.85,25.9
Top Solder:
  region: 38.648,-22.075 40.248,-23.675 40.248,-35.725 42.498,-37.975 48.798,-37.975 49.198,-38.375 49.198,-39.425 48.898,-39.725 29.598,-39.725 29.098,-39.225 29.098,-22.575 29.598,-22.075
  region: 53.498,-21.975 53.998,-22.475 53.998,-26.775 55.398,-28.175 57.098,-28.175 57.448,-28.525 57.448,-39.425 57.148,-39.725 51.098,-39.725 50.848,-39.475 50.848,-34.375 48.698,-32.225 48.698,-22.575 49.298,-21.975
Bottom Solder:
  rectangle: 55.1,41.75 57.75,44.8
  rectangle: 79.1,41.8 83.5,44.8
  rectangle: 89.35,24.8 91.9,28.5
  rectangle: 30.65,46.4 32.45,48.85
  rectangle: 56.55,3.65 60.45,7.25
  region: 57.248,-30.175 57.448,-30.375 57.448,-39.425 57.148,-39.725 51.098,-39.725 50.848,-39.475 50.848,-33.825 51.048,-33.625 54.298,-33.625 54.748,-33.175 54.748,-30.425 54.998,-30.175
  region: 32.848,-22.075 32.848,-22.425 32.048,-23.225 32.048,-28.775 33.448,-30.175 33.448,-35.875 34.698,-37.125 41.198,-37.125 42.398,-38.325 48.948,-38.325 49.198,-38.575 49.198,-39.425 48.898,-39.725 29.598,-39.725 29.098,-39.225 29.098,-22.425 29.448,-22.075
  region: 30.5,2.05 30.6,1.95 30.6,-0.7 30.4,-0.9 28.25,-0.9 27.45,-0.1 27.45,1.75 27.75,2.05
  region: 45.4,1.7 45.7,1.4 45.7,-0.15 45.15,-0.7 43.05,-0.7 42.7,-0.35 42.7,1.2 43.2,1.7
  region: 40.75,2 41.05,1.7 41.05,-0.35 40.7,-0.7 38.55,-0.7 38.2,-0.35 38.2,1.6 38.6,2
  region: 34.45,2.1 35.15,1.4 35.15,-0.35 34.85,-0.65 32.55,-0.65 32.2,-0.3 32.2,1.65 32.65,2.1
  region: 91.45,34.65 91.9,34.2 91.9,31.6 91.45,31.15 89,31.15 88.55,31.6 88.55,34.35 88.85,34.65
  region: 89.8,14.55 91.45,14.55 91.9,14.1 91.9,11.05 91.35,10.5 89.15,10.5 88.65,11 88.65,14.05 89.2,14.6 89.4,14.6
  region: 91.45,21.3 91.85,20.9 91.85,17.9 91.45,17.5 89.35,17.5 88.55,18.3 88.55,20.55 89.3,21.3
  lines w1: 37.85,-3.05 44.6,-3.05 ; 99.5,12.2 101.2,13.9 102,13.9 ; 104.4,10.65 106.95,10.65 109.7,13.4
  lines w1.5: 38.4,-10.05 43.7,-10.05 ; 42.15,-4.9 44.15,-4.9 ; 47.85,-2.25 48.35,-1.75 ; 48.95,-9 54.35,-9 ; 49.05,-4.35 54.6,-4.35 54.65,-4.3 ; 59.85,-8.65 62.4,-6.1 62.4,-2.75 ; 64.45,-0.35 68,-0.35 69.25,0.9 ; 64.5,1.55 66.8,1.55 67.65,2.4 68.75,3.5 68.75,11.65 ; 67.25,22.45 68.55,22.45 ; 82.4,25.55 83.95,24 ; 86.2,26.15 86.2,30.4 87.65,31.85 ; 103.5,8.7 103.95,8.25 104.45,8.25
Mechanical 1:
  lines w0.1: 98.411,17.724 98.411,14.191 cw(c98.243,13.95) 98.011,13.771 95.786,13.771 95.786,11.551 98.011,11.551 cw(c98.251,11.382) 98.431,11.15 98.431,-1.375 ; 98.42,17.724 ccw(c98.24,17.956) 98,18.125 95.776,18.125 95.776,20.345 98,20.345 ccw(c98.232,20.525) 98.401,20.765 98.401,25.249 ccw(c98.221,25.481) 97.981,25.65 95.756,25.65 95.756,27.87 97.981,27.87 ccw(c98.213,28.05) 98.381,28.29 98.381,31.625 ccw(c98.202,31.857) 97.961,32.026 95.737,32.026 95.737,34.275 118.3,34.275 118.3,-1.375 98.45,-1.375 ; 28.6,-40.25 31.395,-40.25 57.97,-40.25 57.97,-18.625 55.746,-18.625 55.746,-20.83 cw(c55.577,-21.07) 55.345,-21.25 53.441,-21.25 cw(c53.2,-21.081) 53.021,-20.849 53.021,-18.625 50.796,-18.625 50.796,-20.849 cw(c50.628,-21.09) 50.396,-21.269 47.945,-21.269 cw(c47.705,-21.101) 47.525,-20.869 47.525,-18.625 45.301,-18.625 45.301,-20.869 cw(c45.132,-21.109) 44.9,-21.289 43.47,-21.289 cw(c43.23,-21.12) 43.05,-20.888 43.05,-18.625 40.826,-18.625 40.826,-20.888 cw(c40.657,-21.128) 40.425,-21.308 37.295,-21.308 cw(c37.055,-21.139) 36.875,-20.907 36.875,-18.625 34.651,-18.625 34.651,-20.907 cw(c34.482,-21.148) 34.25,-21.327 33.022,-21.327 cw(c32.782,-21.159) 32.602,-20.927 32.602,-18.644 30.401,-18.644 30.395,-18.65 30.395,-21.308 28.6,-21.308 28.6,-40.25
  lines w0.127: 24.825,-9.833 24.825,51.367 ; 24.825,-9.833 25.325,-11.833 ; 24.825,-9.833 24.825,51.367 ; 24.825,-9.833 25.325,-11.833 ; 24.825,51.367 25.325,53.367 ; 24.825,51.367 25.325,53.367 ; 25.325,-11.833 63.825,-11.833 63.825,-1.833 93.325,-1.833 ; 25.325,53.367 93.325,53.367 ; 93.325,-1.833 93.825,0.167 ; 93.325,-1.833 93.825,0.167 ; 93.325,53.367 93.825,51.367 ; 93.325,53.367 93.825,51.367 ; 93.825,0.167 93.825,51.367 ; 93.825,0.167 93.825,51.367
Mechanical 2:
  lines w0.1: 38.05,46.65 38.05,81.95 ; 41.35,44.35 41.35,82.35 ; 51.225,42.25 51.225,83.1 ; 99.7,27.15 120.45,27.15
  lines w1.2: 40.75,23.15 41.85,23.15 43.45,23.15 43.5,23.2 44.75,24.45 46.8,24.45
  lines w1.5: 31.95,5.55 31.95,2.6 31.4,2.05 31.4,-0.7 32.2,-1.5 35.1,-1.5 ; 32.95,-4.95 34.65,-6.65 58.6,-6.65 60.7,-4.55 60.7,2.35 61.6,3.25 65.5,3.25 66.9,4.65 66.9,11.6 65.95,12.55 64.2,12.55 63.55,13.2 63.55,23.65 62.85,24.35 61.05,24.35 59.1,22.4 56.95,22.4 ; 37.35,5.45 35.2,5.45 34.75,5 34.75,3.05 35.7,2.1 37.35,2.1 38.8,3.55 38.8,4.7 ; 39.6,-1.7 39.75,-1.55 45.6,-1.55 46.55,-0.6 46.55,2.05 ; 41.748,-24.725 41.198,-25.275 41.198,-36.075 42.698,-37.575 49.448,-37.575 50.098,-36.925 50.098,-34.475 47.798,-32.175 47.798,-25.775 49.248,-24.325 49.248,-21.375 ; 41.85,-0.55 41.85,1.35 42.95,2.45 44.65,2.45 ; 52.2,16 53.95,16 55.05,17.1 55.05,18.35 ; 52.5,11.65 52.5,9.05 55.45,6.1 55.45,3.55 57,2 ; 54.848,-23.425 54.848,-26.425 55.648,-27.225 57.598,-27.225 ; 56.45,12.15 56.45,13.85 57.65,15.05 59.4,15.05 60.4,16.05 60.4,18.45 ; 56.6,10.55 56.6,9.35 57.3,8.65 57.65,8.3 58.9,8.3 59.5,8.3 60.3,9.1 60.45,9.25 60.45,10.9 59.7,11.65 58.5,11.65 ; 59.8,28.25 63.95,28.25 65.5,26.7 68.95,26.7 69.75,25.9 69.75,24.85 78.1,16.5 ; 68.95,29.5 71.85,26.6 71.85,25.55 75.55,21.85 79.75,21.85 ; 88.15,24.55 88.15,28.55 89.4,29.8 91.05,29.8 ; 96.15,29.7 97.7,29.7 99.35,28.05 99.35,25.35 ; 98.1,30.6 99.3,31.8 99.3,35.85 99.65,36.2 ; 102.5,6.55 100.8,8.25 100.8,11.25 101.55,12 105.25,12 106.9,13.65 ; 103.9,34.3 103.9,30.95 104.6,30.25 107.95,30.25 108.6,30.9 108.6,34.7 108.55,34.75
  lines w2: 106.9,13.65 106.9,14.15 ; 108.75,9.45 111.2,11.9 113.45,11.9 116.1,14.55 119.25,14.55
  lines w3.2: 112.975,-3.375 113.4,-2.95 113.4,5.4 115.05,7.05 118.475,7.05
  lines w7: 22.7,33.95 24.4,32.25 38.8,32.25 44.75,38.2 94.45,38.2 94.85,38.6
  text "板厚1.2mm  2OZ   4层板" at 54.55,58.95 h2
  text "板厚1.2mm  2OZ   2层板" at 110.45,37.75 h2
  text "板厚1.2mm  2OZ   2层板" at 38.75,-16.075 h2
Mechanical 15:
  lines w0.127: 25.325,-11.833 25.825,-11.833 ; 25.325,53.367 25.825,53.367 ; 92.825,-1.833 93.325,-1.833 ; 92.825,53.367 93.325,53.367
Mechanical 16:
  circle w0.064: c93.825,63.289 r0.032
  circle w0.064: c93.825,47.7 r0.032
Drill Drawing:
  text ".legend" at 42.65,59.15 h1.52
  text ".legend" at 98.55,37.95 h1.52
  text ".legend" at 26.85,-15.875 h1.52

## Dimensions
25.325,53.367 to 25.325,-11.833 on Drill Drawing
24.825,51.367 to 93.825,51.367 on Drill Drawing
